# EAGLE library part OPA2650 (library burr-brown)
Dual Wideband, Low Power Voltage Feedback Operational Amplifier
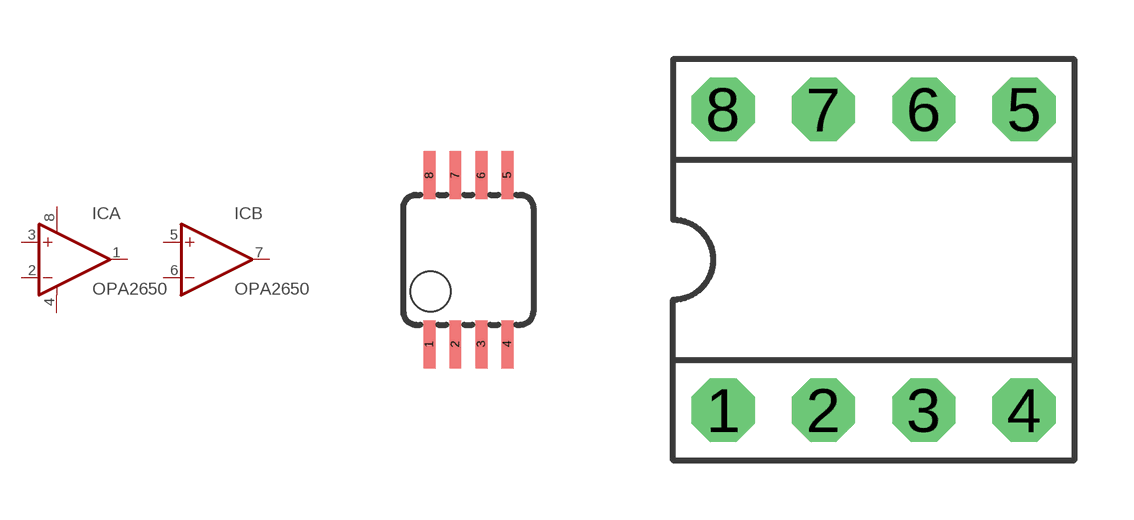
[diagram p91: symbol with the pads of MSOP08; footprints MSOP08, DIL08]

Designator prefix IC; gates A=OP-AMP+- B=OP-AMP

## OPA2650E (OC_FARNELL: unknown; OC_NEWARK: unknown)  [MSOP08]
1  A:OUT  out
2  A:-IN  in
3  A:+IN  in
4  A:V-  pwr
5  B:+IN  in
6  B:-IN  in
7  B:OUT  out
8  A:V+  pwr

## OPA2650P (MPN: AD8056ANZ; OC_FARNELL: 1079308; OC_NEWARK: 19M0925)  [DIL08]
Pads as for MSOP08

## OPA2650U (MF: ALTERA CORPORATION; MPN: AD8056ARMZ; OC_FARNELL: 1424046; OC_NEWARK: 59K6306)  [SO08]
Pads as for MSOP08

## Footprint MSOP08 (pad centres in mm)
Mini Small Outline Package
smd 0.3 x 1.2: 1 -0.976,-2.113; 2 -0.326,-2.113; 3 0.324,-2.113; 4 0.974,-2.113; 5 0.974,2.112; 6 0.324,2.112; 7 -0.326,2.112; 8 -0.976,2.112

## Footprint DIL08 (pad centres in mm)
Dual In Line
drill 0.813 pad 1.6 octagon: 1 -3.81,-3.81; 2 -1.27,-3.81; 3 1.27,-3.81; 4 3.81,-3.81; 5 3.81,3.81; 6 1.27,3.81; 7 -1.27,3.81; 8 -3.81,3.81

## Footprint SO08 (pad centres in mm)
Small Outline Package
smd 0.61 x 2.21: 1 -1.905,-2.616; 2 -0.635,-2.616; 3 0.635,-2.616; 4 1.905,-2.616; 5 1.905,2.616; 6 0.635,2.616; 7 -0.635,2.616; 8 -1.905,2.616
